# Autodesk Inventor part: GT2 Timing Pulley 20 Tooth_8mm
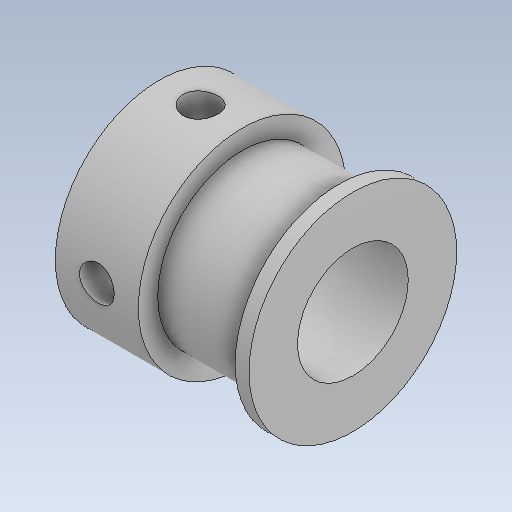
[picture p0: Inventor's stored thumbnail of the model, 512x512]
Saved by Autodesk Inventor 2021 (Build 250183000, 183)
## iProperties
Created: 2026-10
Part Number: GT2 Timing Pulley 20 Tooth_8mm
Material: Steel
Document SubType Name: Modeling
Designer: hp
Density: 7.85 g/cm^3
Appearance: Default
Author: hp
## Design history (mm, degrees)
feature "Body1"
body "Solid1"
